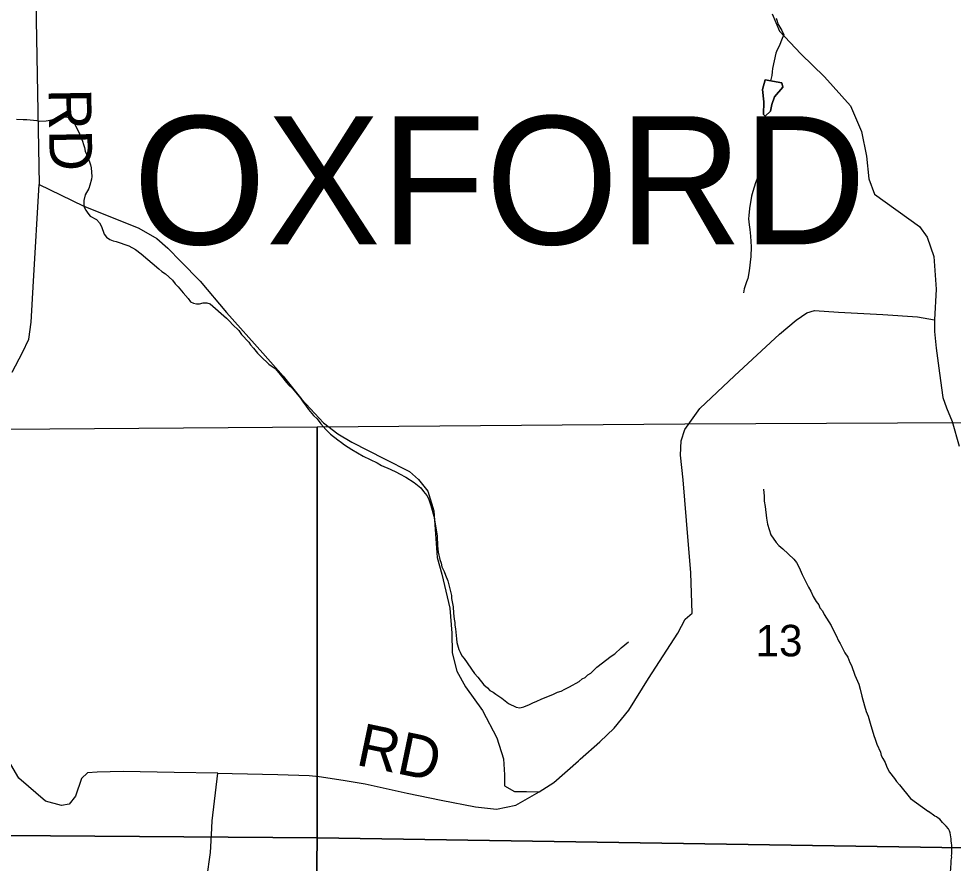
# Model space of a CAD drawing. Extents: x -14196 to 143, y -6096 to 28.
# Drawn here: x 58.822 to 60.064, y 20.825 to 21.949 of the extents above; entities that cross this region are included whole.
import ezdxf

# ---------------------------------------------------------------- set-up
doc = ezdxf.new("R2010")
doc.units = 0
for name, color, linetype in [('GM_X_Corporation', 7, 'Continuous'), ('GM_X_County_Road', 7, 'Continuous'), ('GM_X_Minor_Lake', 7, 'Continuous'), ('GM_X_Minor_River', 7, 'Continuous'), ('GM_X_Section_Text', 7, 'Continuous'), ('GM_X_Township_Road', 7, 'Continuous'), ('GM_X_Township_Road_Text', 7, 'Continuous'), ('GM_X_Township_Text', 7, 'Continuous')]:
    doc.layers.add(name, color=color, linetype=linetype)

msp = doc.modelspace()

# ---------------------------------------------------------------- linework, layer by layer
at = {"layer": 'GM_X_Corporation'}
for points in [[(59.9903, 21.4111), (60.2221, 21.4121), (60.2211, 20.8437), (59.2185, 20.859), (59.2186, 21.4059), (59.7074, 21.4098)], [(58.2114, 21.3981), (59.2186, 21.4059), (59.2185, 20.859), (58.2134, 20.8668), (58.2133, 20.8703)], [(59.2185, 20.859), (59.2056, 19.8463), (58.2013, 19.8806), (58.2134, 20.8668)], [(60.2211, 20.8437), (60.2036, 19.8271), (59.7077, 19.847), (59.2056, 19.8463), (59.2185, 20.859)]]:
    msp.add_lwpolyline(points, close=True, dxfattribs=at)
at = {"layer": 'GM_X_County_Road'}
msp.add_lwpolyline([(59.8233, 21.955), (59.8331, 21.9319), (59.8616, 21.9019), (59.8932, 21.8712), (59.9276, 21.8325), (59.9421, 21.7985), (59.949, 21.7656), (59.9521, 21.7356), (59.9596, 21.7152), (60.0195, 21.6723), (60.0296, 21.658), (60.0386, 21.6323), (60.0415, 21.589), (60.0393, 21.5479), (60.0392, 21.5324), (60.0417, 21.5104), (60.046, 21.477), (60.0506, 21.4448), (60.0553, 21.4308), (60.0628, 21.413), (60.0723, 21.3801)], dxfattribs=at)
at = {"layer": 'GM_X_Minor_Lake'}
for points in [[(59.8143, 21.8674), (59.8107, 21.8544), (59.8123, 21.8381), (59.8121, 21.821), (59.8144, 21.8191), (59.8212, 21.8256)], [(59.8143, 21.8674), (59.8364, 21.863), (59.8376, 21.8573), (59.8267, 21.8447), (59.823, 21.8344), (59.8212, 21.8256), (59.8144, 21.8191), (59.8121, 21.821), (59.8123, 21.8381), (59.8107, 21.8544), (59.8143, 21.8674)], [(59.8212, 21.8256), (59.823, 21.8344), (59.8267, 21.8447), (59.8376, 21.8573), (59.8364, 21.863), (59.8143, 21.8674)]]:
    msp.add_lwpolyline(points, dxfattribs=at)
at = {"layer": 'GM_X_Minor_River'}
for points in [[(59.8287, 21.9492), (59.8303, 21.9454), (59.8311, 21.9416), (59.8365, 21.9329), (59.8388, 21.9269), (59.8366, 21.9223), (59.8329, 21.912), (59.8303, 21.907), (59.8284, 21.9025), (59.8241, 21.8823), (59.8237, 21.8777), (59.823, 21.8731), (59.8215, 21.866)], [(59.8144, 21.8192), (59.813, 21.8104), (59.8123, 21.8058), (59.8124, 21.7967), (59.8114, 21.7841), (59.8114, 21.7788), (59.8107, 21.7746), (59.8101, 21.7651), (59.809, 21.7598), (59.8086, 21.756), (59.8075, 21.7522), (59.8064, 21.7476), (59.8046, 21.7419), (59.8039, 21.7369), (59.8013, 21.7304), (59.7976, 21.7186), (59.7961, 21.7125), (59.7933, 21.6962), (59.7926, 21.6867), (59.7919, 21.6825), (59.7927, 21.6745), (59.7936, 21.6681), (59.7948, 21.6593), (59.7957, 21.6453), (59.7951, 21.6323), (59.793, 21.6133), (59.7912, 21.6031), (59.7893, 21.5985), (59.7864, 21.5893), (59.7853, 21.584)], [(58.8188, 21.8149), (58.8279, 21.8143), (58.8325, 21.8143), (58.8458, 21.8129), (58.85, 21.8122), (58.8584, 21.8127), (58.866, 21.8142), (58.8717, 21.8158), (58.8808, 21.8174), (58.8853, 21.8179), (58.8899, 21.8168), (58.8934, 21.813), (58.8961, 21.8088), (58.8984, 21.8047), (58.9027, 21.7956), (58.9066, 21.7858), (58.9078, 21.7812), (58.9094, 21.7774), (58.9102, 21.7725), (58.9137, 21.7645), (58.9172, 21.7543), (58.918, 21.7501), (58.9189, 21.7388), (58.9186, 21.7349), (58.9164, 21.7269), (58.9149, 21.7228), (58.9104, 21.7144), (58.9086, 21.7067), (58.9086, 21.7022), (58.909, 21.698), (58.911, 21.6938), (58.9137, 21.6897), (58.9168, 21.6859), (58.9252, 21.6814), (58.9294, 21.6769), (58.9318, 21.672), (58.9353, 21.6621), (58.9384, 21.658), (58.943, 21.655), (58.9472, 21.6531), (58.9514, 21.6524), (58.9682, 21.6465), (58.977, 21.6417), (58.9847, 21.636), (59.0081, 21.6157), (59.0123, 21.6124), (59.0169, 21.6094), (59.0261, 21.6007), (59.03, 21.5958), (59.0338, 21.592), (59.0404, 21.5837), (59.047, 21.5762), (59.0504, 21.5721), (59.0542, 21.5702), (59.0581, 21.5695), (59.0622, 21.5695), (59.0672, 21.5707), (59.0718, 21.5704), (59.0763, 21.5693), (59.0982, 21.5501)], [(59.0982, 21.5501), (59.1025, 21.546), (59.1059, 21.5418), (59.1144, 21.5339), (59.1182, 21.5286), (59.1279, 21.5185), (59.1298, 21.5147), (59.134, 21.5105), (59.1394, 21.5038), (59.1437, 21.4992), (59.1544, 21.4891), (59.159, 21.4861), (59.1629, 21.4831), (59.1694, 21.4755), (59.1779, 21.4646), (59.1814, 21.4608), (59.1852, 21.4571), (59.1964, 21.4439), (59.1991, 21.4397), (59.2041, 21.4333), (59.2072, 21.4288), (59.2138, 21.4209), (59.2188, 21.4164), (59.2234, 21.4099), (59.2303, 21.402), (59.2365, 21.396), (59.2461, 21.3885), (59.2511, 21.3847), (59.2549, 21.3817), (59.2649, 21.3754), (59.2798, 21.3668), (59.2985, 21.3578), (59.3043, 21.3545), (59.3157, 21.3496), (59.3242, 21.3455), (59.328, 21.3433), (59.3364, 21.3388), (59.3475, 21.3317), (59.3564, 21.3246), (59.3598, 21.3197), (59.3645, 21.3144), (59.3664, 21.3106), (59.3699, 21.3011), (59.3735, 21.2871), (59.3759, 21.2742), (59.378, 21.2602), (59.3785, 21.2476), (59.3793, 21.2389), (59.3817, 21.2291), (59.3833, 21.2245), (59.3845, 21.2196), (59.3876, 21.2132), (59.3892, 21.2086), (59.3923, 21.2007), (59.395, 21.1904), (59.397, 21.1813), (59.3971, 21.1775), (59.3995, 21.1665), (59.4, 21.1578), (59.4008, 21.1498), (59.4016, 21.1456), (59.4016, 21.1418), (59.4025, 21.1369), (59.4037, 21.1236), (59.4045, 21.1187), (59.4069, 21.1096), (59.4085, 21.1058), (59.4108, 21.1013), (59.4139, 21.0975), (59.4278, 21.0775), (59.4324, 21.0726), (59.4401, 21.0624), (59.4451, 21.0587), (59.4482, 21.0549), (59.4524, 21.053), (59.4563, 21.05), (59.4639, 21.0448), (59.4731, 21.0377), (59.4831, 21.0328), (59.488, 21.0321), (59.4934, 21.0333), (59.5009, 21.0364), (59.5055, 21.0387), (59.5108, 21.0407), (59.5165, 21.0434), (59.5328, 21.05), (59.5381, 21.0527), (59.543, 21.0543), (59.5479, 21.057), (59.554, 21.0597), (59.5669, 21.067), (59.571, 21.0705), (59.5748, 21.0724), (59.5786, 21.0759), (59.5823, 21.0782), (59.5906, 21.0859), (59.6095, 21.1005), (59.6144, 21.104), (59.6227, 21.112), (59.6325, 21.1197)], [(59.812, 21.3228), (59.8128, 21.3137), (59.8129, 21.3069), (59.8141, 21.2996), (59.8158, 21.2841), (59.8174, 21.2761), (59.8217, 21.2621), (59.8287, 21.2519), (59.8322, 21.2478), (59.8375, 21.2436), (59.8525, 21.2297), (59.856, 21.2252), (59.8595, 21.2187), (59.8634, 21.2093), (59.8716, 21.1923), (59.875, 21.187), (59.8782, 21.1802), (59.882, 21.1734), (59.8855, 21.1688), (59.8867, 21.165), (59.8902, 21.1609), (59.8925, 21.156), (59.9018, 21.1416), (59.9053, 21.134), (59.9084, 21.1284), (59.9115, 21.1212), (59.9138, 21.1174), (59.92, 21.1053), (59.9239, 21.0993), (59.9266, 21.0924), (59.929, 21.0883), (59.9333, 21.0754), (59.9387, 21.0633), (59.9407, 21.0569), (59.9427, 21.0474), (59.9463, 21.0345), (59.9486, 21.0269), (59.951, 21.0208), (59.9545, 21.0087), (59.9565, 21.0027), (59.9585, 20.9951), (59.9604, 20.9905), (59.9628, 20.9837), (59.9675, 20.9731), (59.9686, 20.9686), (59.9706, 20.9644), (59.9737, 20.9591), (59.9753, 20.9546), (59.9772, 20.9504), (59.9795, 20.9466), (59.9861, 20.9379), (59.9888, 20.9338), (59.9926, 20.9296), (60.0073, 20.9115), (60.0312, 20.8942)], [(60.0604, 20.8129), (60.0614, 20.8255), (60.0614, 20.8289), (60.0617, 20.8315), (60.0625, 20.8334), (60.0621, 20.8353), (60.0624, 20.8376), (60.0624, 20.8395), (60.0624, 20.8414), (60.0623, 20.8441), (60.0623, 20.8475), (60.0623, 20.8494), (60.0619, 20.8521), (60.0614, 20.8551), (60.0614, 20.8578), (60.061, 20.8604), (60.0606, 20.8631), (60.0602, 20.8657), (60.0594, 20.8684), (60.0578, 20.871), (60.0548, 20.8744), (60.0521, 20.8774), (60.0501, 20.8793), (60.0482, 20.8816), (60.0463, 20.8838), (60.044, 20.8853), (60.0421, 20.8868), (60.0398, 20.8879), (60.0398, 20.8879), (60.0312, 20.8942)]]:
    msp.add_lwpolyline(points, dxfattribs=at)
at = {"layer": 'GM_X_Township_Road'}
for points in [[(58.8372, 22.5073), (58.8369, 22.5064), (58.8357, 22.5016), (58.8352, 22.4955), (58.8351, 22.4903), (58.8354, 22.4844), (58.8352, 22.4657), (58.844, 21.9958), (58.849, 21.7278)], [(58.8133, 21.4784), (58.827, 21.5044), (58.8355, 21.5223), (58.8383, 21.5448), (58.8414, 21.5995), (58.849, 21.7278)], [(58.849, 21.7278), (58.8775, 21.7143), (58.9083, 21.699), (58.9451, 21.6845), (58.9817, 21.67), (59.0053, 21.6562), (59.0203, 21.6433), (59.0374, 21.6256), (59.0631, 21.5994), (59.0983, 21.5577), (59.1463, 21.5035), (59.1735, 21.4732), (59.1984, 21.4421), (59.2269, 21.411), (59.2461, 21.3965), (59.2647, 21.3851), (59.3083, 21.3633), (59.3415, 21.3462), (59.3534, 21.3358), (59.3658, 21.3203), (59.3736, 21.2938), (59.3782, 21.2319), (59.3842, 21.2096), (59.395, 21.1645), (59.3977, 21.1311), (59.3981, 21.1053), (59.4041, 21.0807), (59.4158, 21.0599), (59.4383, 21.0283), (59.4574, 20.9921), (59.4665, 20.9641), (59.4675, 20.9429), (59.4677, 20.9281), (59.4808, 20.9206), (59.4967, 20.9205), (59.5139, 20.9203)], [(59.5681, 20.9636), (59.5945, 20.9867), (59.6136, 21.0048), (59.6331, 21.0287), (59.6592, 21.0712), (59.6786, 21.1011), (59.698, 21.1313), (59.7077, 21.1501), (59.7171, 21.1578), (59.7152, 21.2117), (59.7098, 21.2811), (59.7053, 21.335), (59.7018, 21.368), (59.7027, 21.387), (59.7075, 21.4023), (59.7273, 21.4299), (59.7735, 21.4734), (59.8333, 21.5289), (59.8552, 21.5474), (59.8695, 21.5575), (59.8797, 21.5603), (59.9117, 21.5584), (59.9704, 21.555), (60.0165, 21.5518), (60.0393, 21.5479)], [(59.0865, 20.9453), (59.0287, 20.9461), (58.9605, 20.9474), (58.9263, 20.9466), (58.9134, 20.9456), (58.9051, 20.9379), (58.8974, 20.9146), (58.8888, 20.9039), (58.8789, 20.9019), (58.8575, 20.908), (58.8221, 20.9383), (58.8081, 20.9621)], [(59.0865, 20.9453), (59.1056, 20.9448), (59.1665, 20.9434), (59.208, 20.942), (59.2213, 20.9407), (59.2533, 20.9358), (59.2823, 20.9309), (59.3384, 20.9187), (59.3835, 20.9091), (59.4289, 20.9002), (59.4571, 20.8972), (59.4829, 20.9024), (59.5139, 20.9203), (59.5331, 20.9327), (59.5659, 20.9617), (59.5681, 20.9636)], [(59.072, 20.805), (59.0768, 20.8397), (59.0781, 20.8629), (59.0792, 20.8816), (59.0865, 20.9453)]]:
    msp.add_lwpolyline(points, dxfattribs=at)

# ---------------------------------------------------------------- texts
at = {"layer": 'GM_X_Section_Text'}
msp.add_text('13', height=0.04186, rotation=0, dxfattribs=at).set_placement((59.8015, 21.1005))
at = {"layer": 'GM_X_Township_Road_Text'}
for rotation, p in [(270.9825, (58.8614, 21.8552)), (348.2105, (59.2687, 20.9564))]:
    msp.add_text('RD', height=0.05682, rotation=rotation, dxfattribs=at).set_placement(p)
at = {"layer": 'GM_X_Township_Text'}
msp.add_text('OXFORD', height=0.17045, rotation=0, dxfattribs=at).set_placement((58.9736, 21.6484))

doc.saveas('drawing.dxf')
